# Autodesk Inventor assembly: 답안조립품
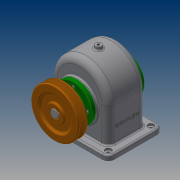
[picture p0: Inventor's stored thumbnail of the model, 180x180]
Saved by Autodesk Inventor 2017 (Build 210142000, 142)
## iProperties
Part Number: 답안조립품
Material: 일반
Document SubType Name: Assembly
Designer: 20
Author: 20
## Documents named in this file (14)
- C:\Users\20\Desktop\480310V1007\답안조립품.iam
- C:\Users\20\Desktop\480310V1007\본체.ipt
- C:\Users\20\Desktop\480310V1007\뒤커버.ipt
- C:\Users\20\Desktop\480310V1007\볼트 M4.ipt
- C:\Users\20\Desktop\480310V1007\앞커버.ipt
- C:\Users\20\Desktop\480310V1007\베어링 6203.ipt
- C:\Users\20\Desktop\480310V1007\축.ipt
- C:\Users\20\Desktop\480310V1007\부시.ipt
- C:\Users\20\Desktop\480310V1007\오일 실 28 40 8.ipt
- C:\Users\20\Desktop\480310V1007\스퍼기어.ipt
- C:\Users\20\Desktop\480310V1007\키 6x6x22.ipt
- C:\Users\20\Desktop\480310V1007\키 5x5x18.ipt
- C:\Users\20\Desktop\480310V1007\멈춤나사 M4.ipt
- C:\Users\20\Desktop\480310V1007\V-벨트풀리.ipt
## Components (1 placed, 1 different names)
1. V-벨트풀리:1 — 플러쉬:2
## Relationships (1: Flush 1)
- 플러쉬:2 [Flush]: V-벨트풀리:1
